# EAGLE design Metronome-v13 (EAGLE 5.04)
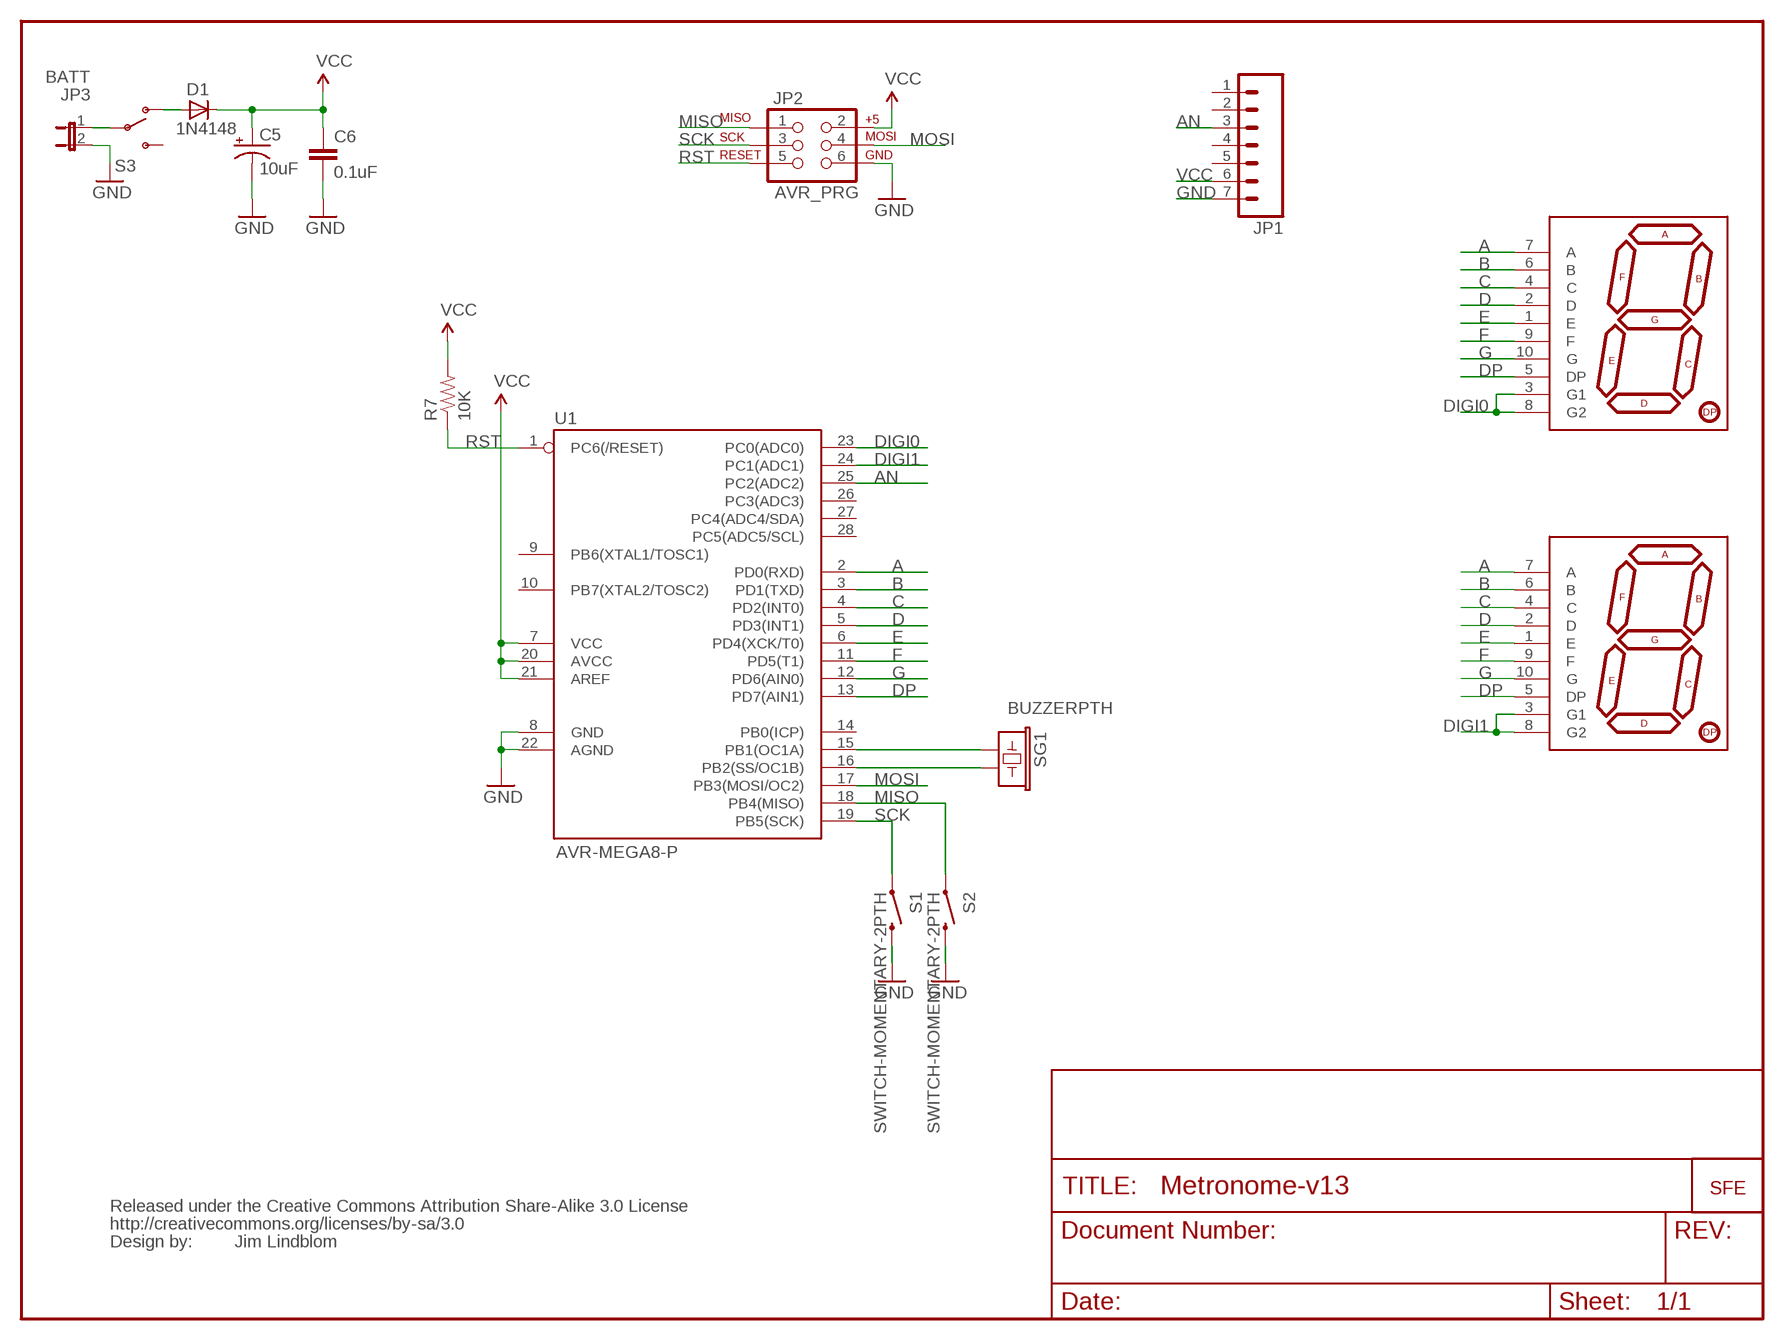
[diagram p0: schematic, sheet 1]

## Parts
C5  10uF  CAP_POLPTH2  [CPOL-RADIAL-10UF-25V]
C6  0.1uF  CAPPTH2  [CAP-PTH-SMALL2]
D1  1N4148  DIODE1N4148  [DIODE-1N4148]
DIGI0  7-SEGMENT-DISPLAY-1"-RED  [7-SEGMENT-1"PTH]
DIGI1  7-SEGMENT-DISPLAY-1"-RED  [7-SEGMENT-1"PTH]
JP1  M07  [1X07]
JP2  AVR_PRG  AVR_SPI_PRG_6PTH  [2X3]
JP3  BATT  JP1E  [1X02]
R7  10K  RESISTORPTH1  [AXIAL-0.3]
S1  SWITCH-MOMENTARY-2PTH  [TACTILE-PTH]
S2  SWITCH-MOMENTARY-2PTH  [TACTILE-PTH]
S3  SWITCH-SPSTPTH_LOCK  [SWITCH-SPDT_LOCK.007S]
SG1  BUZZERPTH  [BUZZER-12MM]
U1  AVR-MEGA8-P  [DIL28-3]
U$1  LOGO-SFENEW  [SFE-NEW-WEBLOGO]
U$2  CREATIVE_COMMONS  [CREATIVE_COMMONS]

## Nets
A: DIGI0.7(A) DIGI1.7(A) U1.2(PD0(RXD))
AN: JP1.3 U1.25(PC2(ADC2))
B: DIGI0.6(B) DIGI1.6(B) U1.3(PD1(TXD))
C: DIGI0.4(C) DIGI1.4(C) U1.4(PD2(INT0))
D: DIGI0.2(D) DIGI1.2(D) U1.5(PD3(INT1))
DIGI0: DIGI0.3(G1) DIGI0.8(G2) U1.23(PC0(ADC0))
DIGI1: DIGI1.3(G1) DIGI1.8(G2) U1.24(PC1(ADC1))
DP: DIGI0.5(DP) DIGI1.5(DP) U1.13(PD7(AIN1))
E: DIGI0.1(E) DIGI1.1(E) U1.6(PD4(XCK/T0))
F: DIGI0.9(F) DIGI1.9(F) U1.11(PD5(T1))
G: DIGI0.10(G) DIGI1.10(G) U1.12(PD6(AIN0))
GND: C5.2(-) C6.2 JP1.7 JP2.6 JP3.2 S1.3 S2.3 U1.8(GND) U1.22(AGND)
MISO: JP2.1 S2.1 U1.18(PB4(MISO))
MOSI: JP2.4 U1.17(PB3(MOSI/OC2))
N$1: JP3.1 S3.2(P)
N$2: D1.A S3.1(O)
N$5: SG1.+ U1.15(PB1(OC1A))
N$6: SG1.- U1.16(PB2(SS/OC1B))
RST: JP2.5 R7.P$1 U1.1(PC6(/RESET))
SCK: JP2.3 S1.1 U1.19(PB5(SCK))
VCC: C5.1(+) C6.1 D1.C JP1.6 JP2.2 R7.P$2 U1.7(VCC) U1.20(AVCC) U1.21(AREF)
Unconnected: JP1.1 JP1.2 JP1.4 JP1.5 S3.3(S) U1.9(PB6(XTAL1/TOSC1)) U1.10(PB7(XTAL2/TOSC2)) U1.14(PB0(ICP)) U1.26(PC3(ADC3)) U1.27(PC4(ADC4/SDA)) U1.28(PC5(ADC5/SCL))

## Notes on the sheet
- Jim Lindblom

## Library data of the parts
C5 = SparkFun:CAP_POL: Capacitor Polarized
C6 = SparkFun:CAP: Capacitor
D1 = SparkFun:DIODE: Diode
DIGI0 DIGI1 = SparkFun:7-SEGMENT-DISPLAY-1"-RED: 7-Segment Display 1" Red (COM-08546)
JP1 = SparkFun:M07: Header 7 Standard 7-pin 0.1" header. Use with straight break away headers (SKU : PRT-00116), right angle break away headers (PRT-00553), swiss pins (PRT-00743), machine pins (PRT-00117), and female headers (PRT-00115). NOTES ON THE VARIANTS LOCK and LOCK_LONGPADS... This footprint was designed to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
JP2 = SparkFun:AVR_SPI_PRG_6: AVR ISP 6 Pin This is the reduced ISP connector for AVR programming. Common on Arduino. This footprint will take up less PCB space and can be used with a 10-pin to 6-pin adapter such as SKU: BOB-08508
JP3 = SparkFun:JP1E: Jumper
R7 = SparkFun:RESISTOR: Resistor
S1 S2 = SparkFun:SWITCH-MOMENTARY-2
S3 = SparkFun:SWITCH-SPST: SPST Switch Simple slide switch. Spark Fun Electronics SKU : COM-00102
SG1 = SparkFun:BUZZER: Buzzer 12mm
U1 = SparkFun:AVR-MEGA8-P: MICROCONTROLLER 8 Kbytes FLASH 1 kbytes SRAM 512 bytes EEPROM USART 4-channel 10 bit ADC 2-channel 8 bit ADC
U$1 = SparkFun:LOGO-SFE: Spark Fun Electronics PCB Logo
U$2 = SparkFun:CREATIVE_COMMONS

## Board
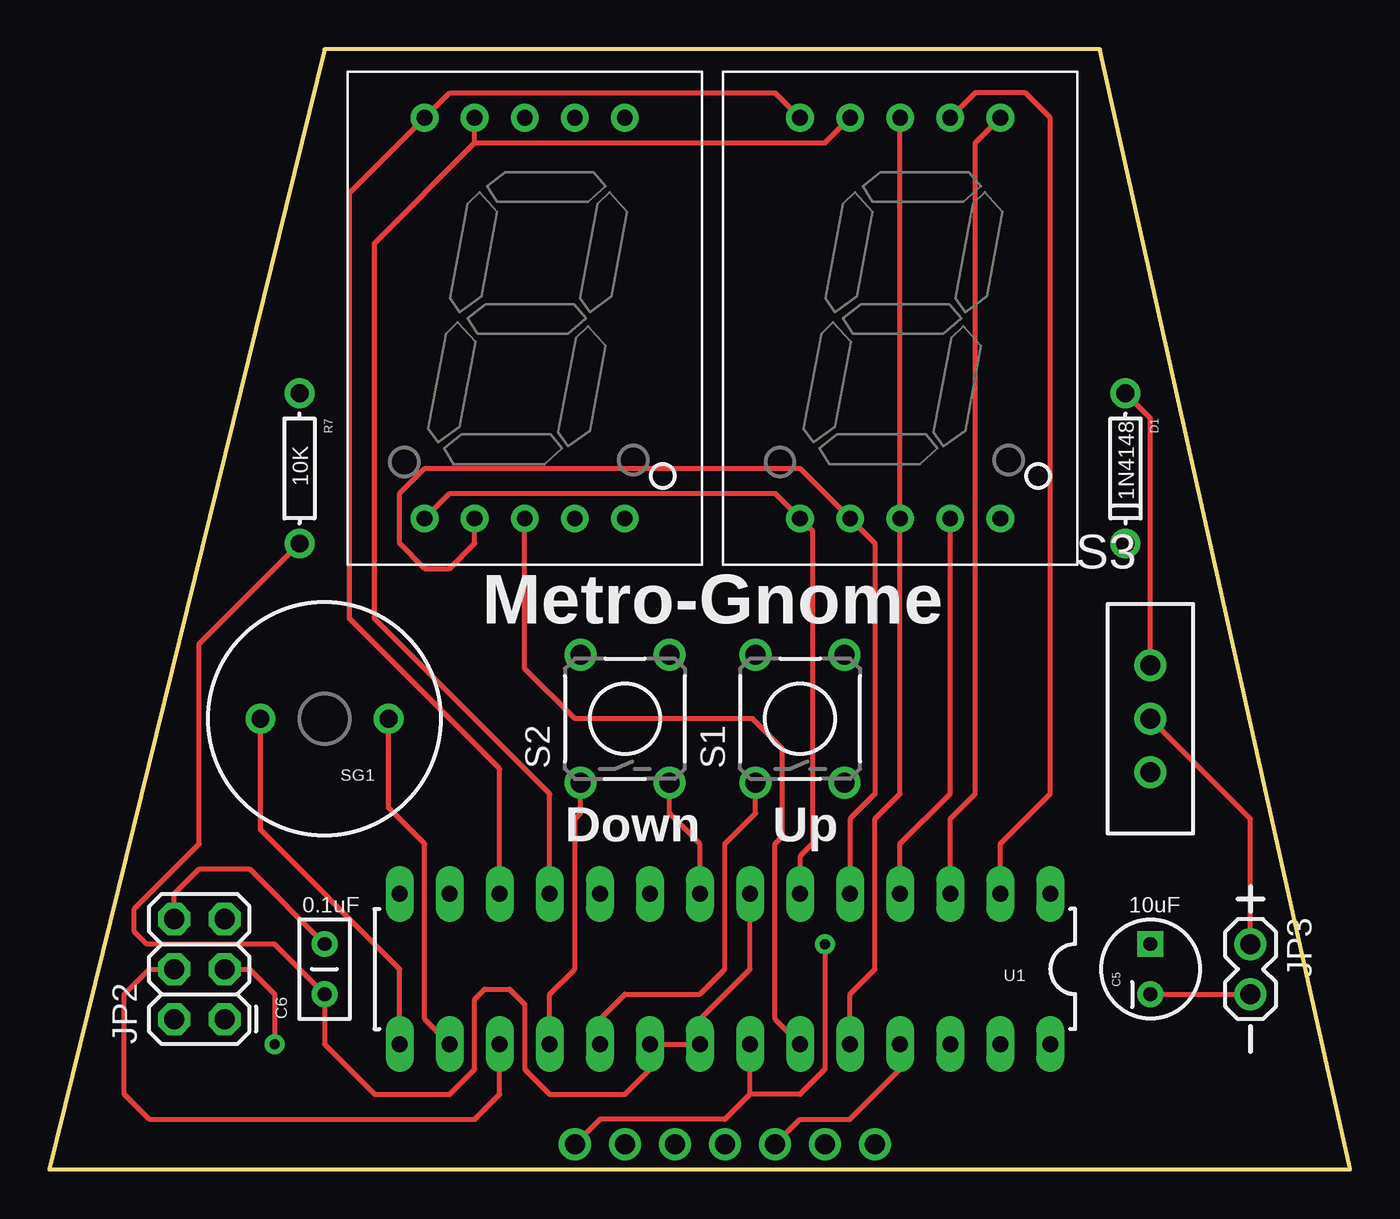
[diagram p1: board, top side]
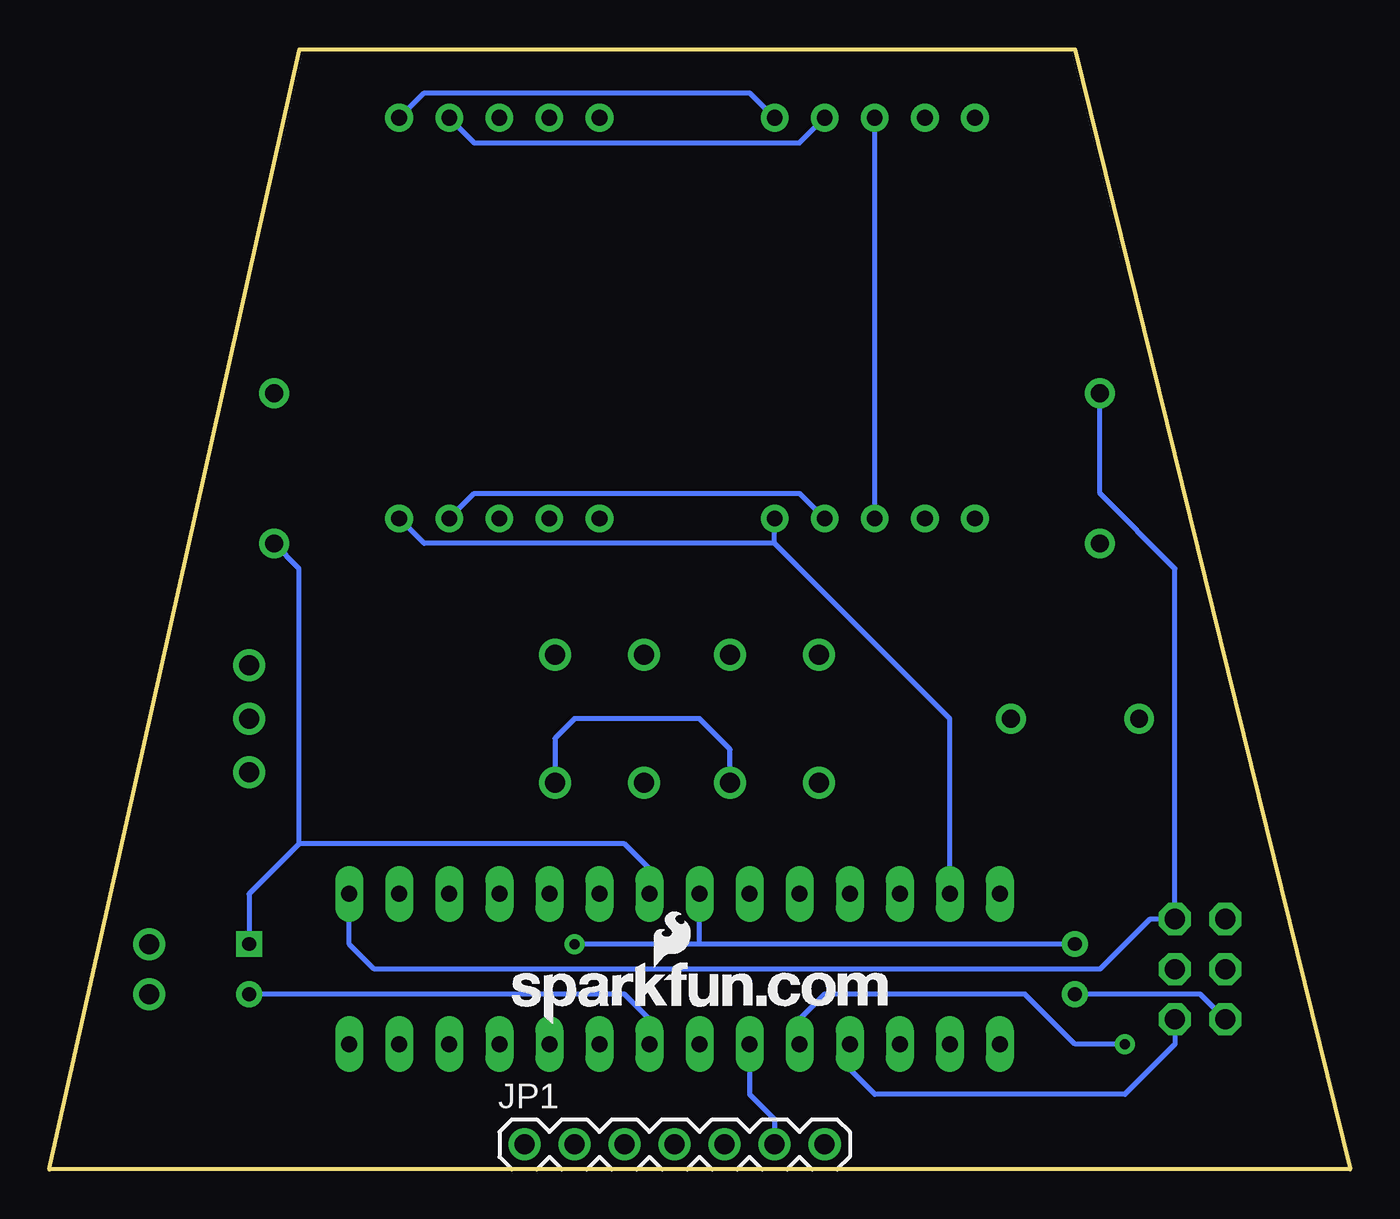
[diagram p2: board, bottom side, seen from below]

Size 66.02 x 56.82 mm. Coordinates in mm from the lower left corner, seen from the top.
Outline: 0,0 66.02,0 53.32,56.82 13.97,56.82 0,0
Copper layers (1*16): Top 0.035mm / dielectric 1.5mm / Bottom 0.035mm
Design rules "SparkFun": minimum track width 8mil, minimum drill 20mil, track to track 8mil, track to pad 8mil, pad to pad 8mil, via to via 8mil, smd to smd 8mil, copper to edge 10mil, drill to drill 8mil, minimum pad ring 12mil, minimum via ring 10mil, stop-mask expansion 4mil, vias tented up to drill 25mil, thermal gap 10mil

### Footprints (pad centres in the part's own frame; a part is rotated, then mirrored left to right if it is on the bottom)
CPOL-RADIAL-10UF-25V = drill 0.7 square: 1 1.27,0 | drill 0.7 round: 2 -1.27,0
CAP-PTH-SMALL2 = drill 0.7 round: 1 0,0; 2 2.54,0
DIODE-1N4148 = drill 0.9 round: A -3.81,0; C 3.81,0
7-SEGMENT-1"PTH = drill 0.8 round: 1 -5.08,-10.16; 2 -2.54,-10.16; 3 0,-10.16; 4 2.54,-10.16; 5 5.08,-10.16; 6 5.08,10.16; 7 2.54,10.16; 8 0,10.16; 9 -2.54,10.16; 10 -5.08,10.16
1X07 = drill 1.016 round: 1 0,0; 2 2.54,0; 3 5.08,0; 4 7.62,0; 5 10.16,0; 6 12.7,0; 7 15.24,0
2X3 = drill 1.016 octagon: 1 0,0; 2 0,2.54; 3 2.54,0; 4 2.54,2.54; 5 5.08,0; 6 5.08,2.54
1X02 = drill 1.016 round: 1 0,0; 2 2.54,0
AXIAL-0.3 = drill 0.9 round: P$1 -3.81,0; P$2 3.81,0
TACTILE-PTH = drill 1.016 round: 1 -3.251,2.261; 2 3.251,2.261; 3 -3.251,-2.261; 4 3.251,-2.261
SWITCH-SPDT_LOCK.007S = drill 1.016 round: 1 0,2.718; 2 0,0; 3 0,-2.718
BUZZER-12MM = drill 0.9 round: + 3.25,0; - -3.25,0
DIL28-3 = drill 0.813 long: 1 -16.51,-3.81; 2 -13.97,-3.81; 3 -11.43,-3.81; 4 -8.89,-3.81; 5 -6.35,-3.81; 6 -3.81,-3.81; 7 -1.27,-3.81; 8 1.27,-3.81; 9 3.81,-3.81; 10 6.35,-3.81; 11 8.89,-3.81; 12 11.43,-3.81; 13 13.97,-3.81; 14 16.51,-3.81; 15 16.51,3.81; 16 13.97,3.81; 17 11.43,3.81; 18 8.89,3.81; 19 6.35,3.81; 20 3.81,3.81; 21 1.27,3.81; 22 -1.27,3.81; 23 -3.81,3.81; 24 -6.35,3.81; 25 -8.89,3.81; 26 -11.43,3.81; 27 -13.97,3.81; 28 -16.51,3.81

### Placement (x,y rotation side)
C5  55.88,10.16 90 top
C6  13.97,8.89 90 top
D1  54.61,35.56 270 top
DIGI0  24.13,43.18 0 top
DIGI1  43.18,43.18 0 top
JP1  41.91,1.27 0 bottom
JP2  8.89,7.62 90 top
JP3  60.96,11.43 270 top
R7  12.7,35.56 270 top
S1  38.1,22.86 90 top
S2  29.21,22.86 90 top
S3  55.88,22.86 0 top
SG1  13.97,22.86 180 top
U1  34.29,10.16 180 top
U$1  42.55,7.37 0 bottom
U$2  not placed on the board

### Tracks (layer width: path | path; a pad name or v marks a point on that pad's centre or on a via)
A
  Top 0.254: U1.2 48.26,16.51 50.8,19.05 50.8,34.29 50.8,53.34 49.53,54.61 46.99,54.61 DIGI1.7
  Bottom 0.254: DIGI0.7 27.94,52.07 44.45,52.07 DIGI1.7
AN
  Top 0.254: JP1.3 38.1,2.54 40.64,2.54 43.18,5.08 U1.25
B
  Top 0.254: U1.3 45.72,17.78 46.99,19.05 46.99,52.07 DIGI1.6
  Bottom 0.254: DIGI0.6 30.48,54.61 46.99,54.61 DIGI1.6
C
  Top 0.254: DIGI1.4 45.72,19.05 43.18,16.51 U1.4
  Bottom 0.254: DIGI0.4 27.94,34.29 44.45,34.29 DIGI1.4
D
  Top 0.254: U1.5 40.64,17.78 41.91,19.05 41.91,31.75 DIGI1.2 38.1,35.56 19.05,35.56 17.78,34.29 17.78,31.75 19.05,30.48 20.32,30.48 21.59,31.75 DIGI0.2
DIGI0
  Top 0.254: DIGI0.3 24.13,25.4 26.67,22.86 35.69,22.86 37.21,21.34 37.21,16.89 36.83,16.51 36.83,7.62 U1.23
  Bottom 0.254: DIGI0.3 DIGI0.8
DIGI1
  Top 0.254: DIGI1.8 DIGI1.3 43.18,19.05 41.91,17.78 41.91,10.16 40.64,8.89 U1.24
DP
  Bottom 0.254: DIGI1.5 46.99,31.75 29.21,31.75 | 29.21,31.75 20.32,22.86 U1.13 | 29.21,31.75 DIGI0.5
E
  Top 0.254: DIGI0.1 20.32,34.29 36.83,34.29 DIGI1.1 38.73,32.38 38.73,16.51 38.1,15.88 U1.6
F
  Top 0.254: DIGI1.9 39.37,52.07 21.59,52.07 | U1.11 25.4,19.05 16.51,27.94 16.51,46.99 21.59,52.07 | 21.59,52.07 DIGI0.9
G
  Top 0.254: DIGI1.10 36.83,54.61 20.32,54.61 DIGI0.10 15.24,49.53 15.24,27.94 22.86,20.32 U1.12
GND  (via drill 0.51)
  Top 0.254: JP2.6 6.35,13.97 7.62,15.24 10.16,15.24 C6.2 | C5.2 JP3.2 | S2.3 31.47,18.06 33.02,16.51 U1.8 | v39.37,11.43 39.37,5.08 38.1,3.81 35.56,3.81 | JP1.7 27.94,2.54 34.29,2.54 35.56,3.81 | 35.56,3.81 U1.22
  Bottom 0.254: S2.3 31.47,21.31 33.02,22.86 39.37,22.86 40.36,21.87 S1.3 | C6.2 33.02,11.43 | 33.02,11.43 v39.37,11.43 | 33.02,11.43 U1.8 | C5.2 36.83,8.89 35.56,7.62 U1.22
MISO
  Top 0.254: S2.1 26.95,18.06 26.67,17.78 26.67,10.16 25.4,8.89 U1.18
  Bottom 0.254: JP2.1 8.89,6.35 11.43,3.81 24.13,3.81 25.4,5.08 U1.18
MOSI
  Top 0.254: JP2.4 5.08,10.16 3.81,8.89 3.81,3.81 5.08,2.54 21.59,2.54 22.86,3.81 U1.17
N$1
  Top 0.254: JP3.1 60.96,17.78 S3.2
N$2
  Top 0.254: S3.1 55.88,38.1 D1.A
N$5
  Top 0.254: SG1.+ 10.72,17.22 17.78,10.16 U1.15
N$6
  Top 0.254: SG1.- 17.22,18.34 19.05,16.51 19.05,7.62 U1.16
RST
  Bottom 0.254: R7.P$1 12.7,34.29 8.89,30.48 JP2.5 10.16,12.7 12.7,10.16 49.53,10.16 50.8,11.43 U1.1
SCK  (via drill 0.51)
  Top 0.254: S1.1 35.84,18.06 34.29,16.51 34.29,10.16 33.02,8.89 29.21,8.89 27.94,7.62 U1.19 | JP2.3 10.16,10.16 11.43,8.89 v11.43,6.35
  Bottom 0.254: v11.43,6.35 13.97,6.35 16.51,8.89 26.67,8.89 27.94,7.62 U1.19
VCC
  Top 0.254: U1.7 35.56,10.16 33.02,7.62 U1.21 U1.20 30.48,5.08 29.21,3.81 25.4,3.81 24.13,5.08 24.13,8.38 23.37,9.14 22.1,9.14 21.59,8.64 21.59,5.08 20.32,3.81 16.51,3.81 13.97,6.35 C6.1 11.43,11.43 4.95,11.43 4.32,12.06 4.32,13.21 7.62,16.51 7.62,26.67 R7.P$2
  Bottom 0.254: JP2.2 7.62,8.89 C6.1 | D1.C 53.34,30.48 53.34,16.51 | U1.7 35.56,15.24 36.83,16.51 53.34,16.51 | JP1.6 29.21,2.54 30.48,3.81 U1.20 | 53.34,16.51 55.88,13.97 C5.1

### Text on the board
tPlace: Metro-Gnome | Down | Up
